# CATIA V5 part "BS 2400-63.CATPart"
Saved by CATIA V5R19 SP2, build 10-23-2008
Part number: BS 2400-63
Bounding box of the stored display mesh (mm): x -37.351 to 37.351, y -37.351 to 37.351, z 0 to 171
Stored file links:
  C:\Users\Bora\Desktop\3D Katı model\BS serisi\BS 2400\BS 2400-63.CATPart
  C:\Program Files\Dassault Systemes\B19\intel_a\reffiles\standard\MetricThickPitch.txt
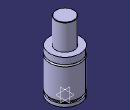
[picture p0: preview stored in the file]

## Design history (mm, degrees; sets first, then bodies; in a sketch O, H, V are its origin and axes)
Body1 (main body)
  Sketch1 on yz-plane, origin (0, 0, 0), H (0, 1, 0), V (0, 0, 1)
    point P1 (22.5, 170)
    point P3 (22.5, 170)
    point P7 (37.5, 91.5)
    point P9 (37.5, 91.5)
    point P10 (37.5, 86.5)
    point P14 (37.5, 86.5)
    line L1 (22.5, 170) -> (22.5, 107)
    arc A1 centre (21.5, 170) radius 1 from (22.5, 170) to (21.5, 171) ccw
    line L2 (37.5, 0) -> (37.5, 8)
    line L3 (37.5, 91.5) -> (37.5, 107)
    arc A2 centre (37.5, 89) radius 2.5 from (37.5, 91.5) to (37.5, 86.5) ccw
    line L4 (34.5, 13) -> (34.5, 8)
    line L5 (37.5, 13) -> (37.5, 86.5)
    line L6 (21.5, 171) -> (0, 171)
    point P15 (0, 171)
    line L7 (22.5, 107) -> (37.5, 107)
    line L8 (0, 0) -> (37.5, 0)
    line L9 (34.5, 13) -> (37.5, 13)
    line L10 (34.5, 8) -> (37.5, 8)
    coincidence: P15 V, P1 P3, P7 P9, P10 P14
    tangency: L6 A1
    horizontal: L7 H, L8 H, L9 H, L10 H
  Shaft1: profile Sketch1, axis Sketch1.V, angle 360
  Sketch2 on face of Shaft1 from Sketch1.L8, origin (0, 0, 0), H (1, 0, 0), V (0, -1, 0)
    point P1 (20, 0)
    distance P1 V = 20
  Hole1: placed by Sketch2, at (20, 0, 0) direction (0, 0, 1), diameter 6.647, depth 5, threaded "M8", thread diameter 8, thread depth 5, pitch 1.25
  CircPattern1: of Hole1, instances 4, angular step 90, axis from xy-plane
